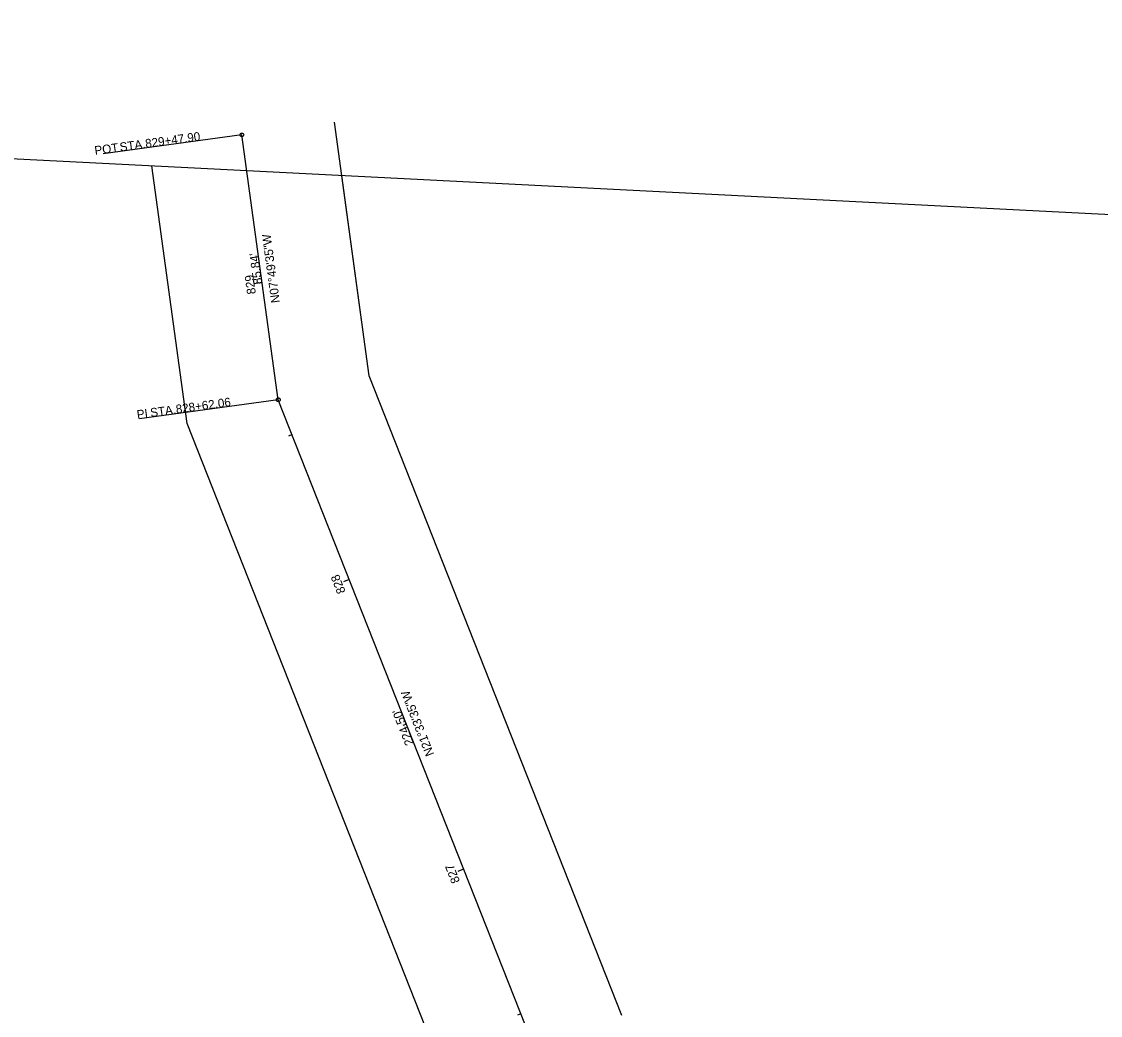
# Model space of a CAD drawing. Extents: x 2376935 to 2379466, y 252990 to 254108.
# Drawn here: x 2377853.9 to 2378200.5, y 253788.5 to 254107.6 of the extents above; entities that cross this region are included whole.
import ezdxf

# ---------------------------------------------------------------- set-up
doc = ezdxf.new("R2010")
doc.units = 0
for name, color, linetype in [('_CIVIL_CONSTRUCTION', 7, 'Continuous'), ('PF_X_Ground_Line', 7, 'Continuous'), ('SC_Scratch1', 7, 'Continuous'), ('SC_Scratch2', 7, 'Continuous'), ('SN_X_Public', 7, 'Continuous'), ('UT_X_Electric', 7, 'Continuous'), ('UT_X_FO', 7, 'Continuous')]:
    doc.layers.add(name, color=color, linetype=linetype)

msp = doc.modelspace()

# ---------------------------------------------------------------- linework, layer by layer
at = {"layer": '_CIVIL_CONSTRUCTION'}
for p, q in [((2377931.22, 254023.8), (2377929.24, 254023.53)), ((2377940.82, 253975), (2377939.7, 253974.56)), ((2377959.19, 253928.49), (2377957.33, 253927.76)), ((2377977.57, 253881.99), (2377976.45, 253881.55)), ((2377995.94, 253835.49), (2377994.08, 253834.76)), ((2378014.31, 253788.99), (2378013.2, 253788.55))]:
    msp.add_line(p, q, dxfattribs=at)
at = {"layer": 'PF_X_Ground_Line'}
for p, q in [((2377965.62, 253993.88), (2377954.42, 254075.34)), ((2377907.16, 253978.55), (2377895.78, 254061.35)), ((2377965.62, 253993.88), (2377956.77, 254058.25)), ((2378046.78, 253788.45), (2377965.62, 253993.88)), ((2377990.98, 253766.4), (2377907.16, 253978.55)), ((2377990.98, 253766.4), (2377907.16, 253978.55))]:
    msp.add_line(p, q, dxfattribs=at)
at = {"layer": 'SC_Scratch1'}
for p, q in [((2377924.7, 254071.25), (2377880.12, 254065.12)), ((2377936.39, 253986.22), (2377891.81, 253980.09))]:
    msp.add_line(p, q, dxfattribs=at)
for centre in [(2377924.7, 254071.25), (2377936.39, 253986.22)]:
    msp.add_circle(centre, 0.6, dxfattribs=at)
at = {"layer": 'UT_X_Electric'}
msp.add_line((2376985.61, 254107.64), (2377926.27, 254059.8), dxfattribs=at)
msp.add_lwpolyline([(2377926.27, 254059.8), (2379466.42, 253981.48), (2379423.44, 253065.34)], dxfattribs=at)
at = {"layer": 'UT_X_FO'}
for p, q in [((2377936.39, 253986.22), (2377924.7, 254071.25)), ((2378018.88, 253777.43), (2377936.39, 253986.22))]:
    msp.add_line(p, q, dxfattribs=at)

# ---------------------------------------------------------------- texts
at = {"layer": '_CIVIL_CONSTRUCTION'}
for s, rotation, p in [('829', 97.8263, (2377929.18, 254020.26)), ('828', 111.5597, (2377958.06, 253924.55)), ('827', 111.5597, (2377994.81, 253831.56))]:
    msp.add_text(s, height=2.8, rotation=rotation, dxfattribs=at).set_placement(p)
at = {"layer": 'SC_Scratch1'}
for s, p in [('829+47.90', (2377893.84, 254067.05)), ('POT', (2377877.54, 254064.81)), (' STA. ', (2377884.6, 254065.78)), ('828+62.06', (2377903.65, 253981.75)), ('PI', (2377891.13, 253980.03)), (' STA. ', (2377894.41, 253980.48))]:
    msp.add_text(s, height=2.8, rotation=7.8263, dxfattribs=at).set_placement(p)
at = {"layer": 'SC_Scratch2'}
for s, rotation, p in [("85.84'", 97.8263, (2377931.23, 254023.46)), ("224.50'", 111.5597, (2377979.97, 253875.82))]:
    msp.add_text(s, height=2.8, rotation=rotation, dxfattribs=at).set_placement(p)
at = {"layer": 'SN_X_Public'}
for s, rotation, p in [('N07°49\'35"W', 97.8263, (2377936.94, 254017.47)), ('N21°33\'35"W', 111.5597, (2377986.52, 253872.4))]:
    msp.add_text(s, height=2.8, rotation=rotation, dxfattribs=at).set_placement(p)

doc.saveas('drawing.dxf')
